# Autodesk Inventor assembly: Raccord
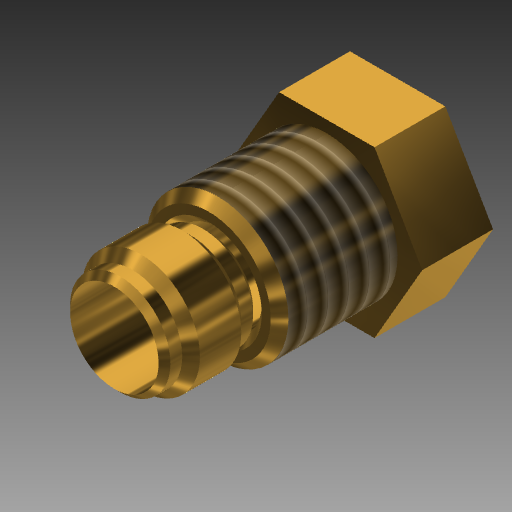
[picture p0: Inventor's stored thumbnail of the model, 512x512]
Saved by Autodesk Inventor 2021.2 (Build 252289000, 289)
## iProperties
Created: 2018-06
Part Number: Raccord
Material: Générique
Document SubType Name: Assembly
Designer: Fabian Perrée
Author: Fabian Perrée
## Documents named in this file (3)
- C:\Users\Fabian\Google Drive\04_CAO\01_Inventor\01_Fichiers_exercice_Inventor\01_Definitif\Capteur\Ens_raccord\Ens_raccord.iam
- C:\Users\Fabian\Google Drive\04_CAO\01_Inventor\01_Fichiers_exercice_Inventor\01_Definitif\Capteur\Ens_raccord\Composants\Bague.ipt
- C:\Users\Fabian\Google Drive\04_CAO\01_Inventor\01_Fichiers_exercice_Inventor\01_Definitif\Capteur\Ens_raccord\Composants\Vis_hexa.ipt
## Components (2 placed, 2 different names)
1. Bague:1
2. Vis_hexa:1
